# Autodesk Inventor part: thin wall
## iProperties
Author: Administrator
Created: 2001-03
Part Number: thin wall
Document SubType Name: Modeling
Designer: Administrator
Control State: 0
Master: False
Checked Out: False
PropertySet Name: Design Tracking Control
Shininess: 20.0
PropertySet Name: _Private Model Information
Density: 0.0
Volumn: 0.0
Area: 0.0
PropertySet Name: Model Information
